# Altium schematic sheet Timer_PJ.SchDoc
size A4
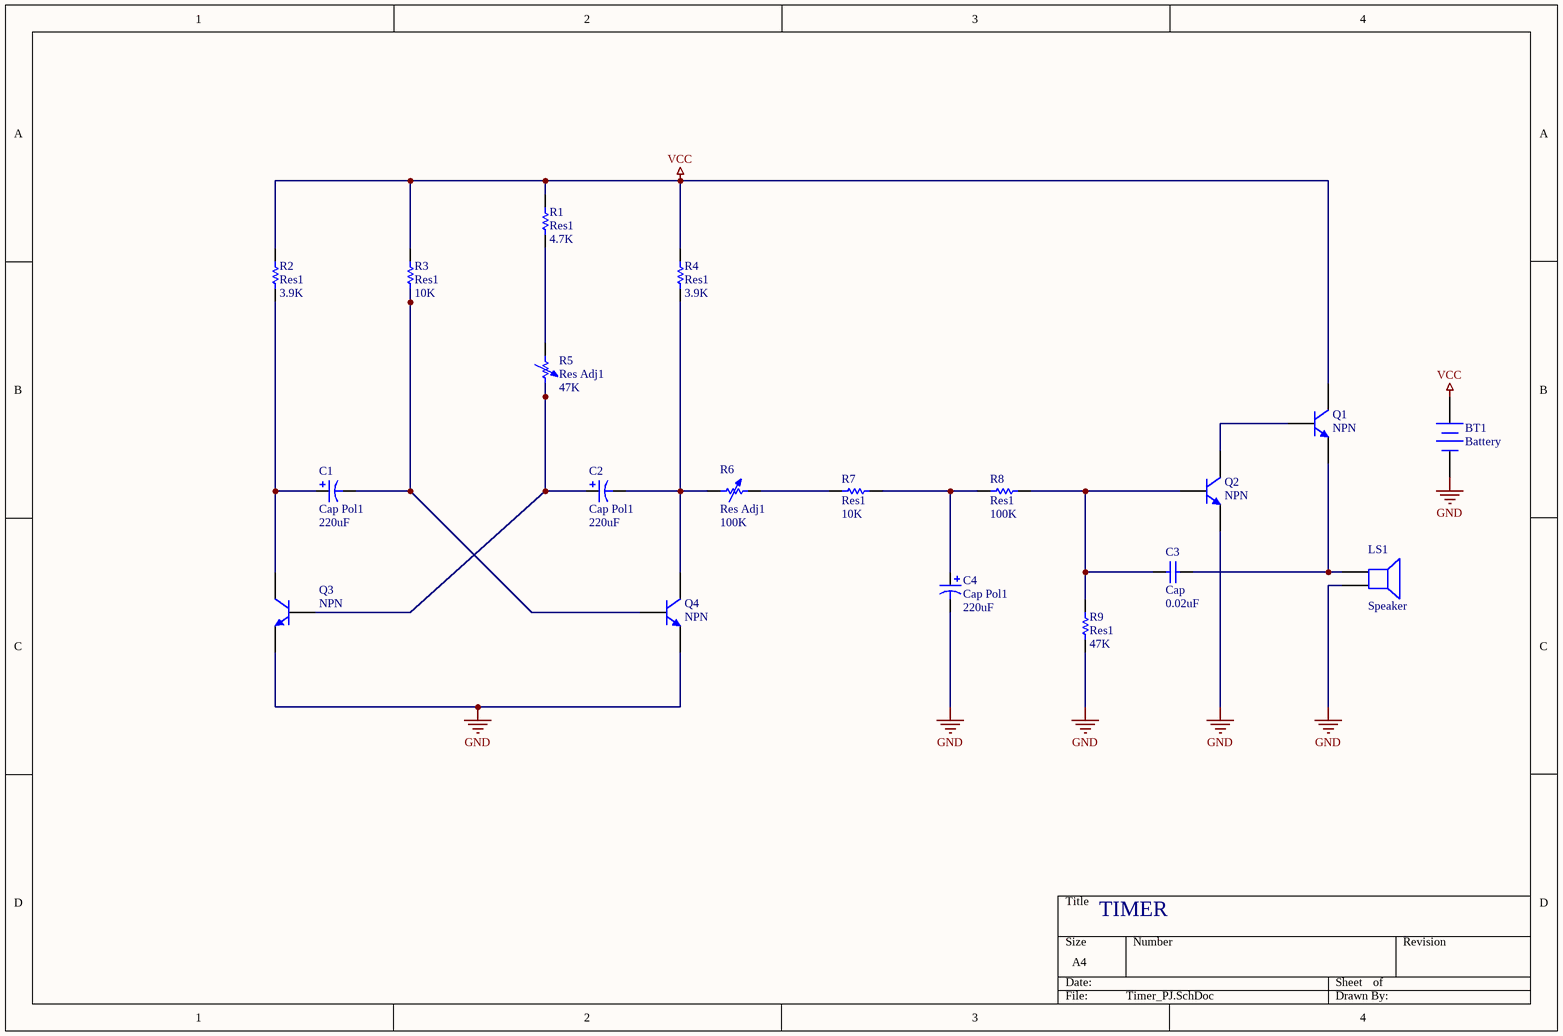
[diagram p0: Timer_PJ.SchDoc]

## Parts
BT1  Battery  [BAT-2]
C1  Cap Pol1  value 220uF  [RB7.6-15]
C2  Cap Pol1  value 220uF  [RB7.6-15]
C3  Cap  value 0.02uF  [RAD-0.3]
C4  Cap Pol1  value 220uF  [RB7.6-15]
LS1  Speaker  [PIN2]
Q1  NPN  [TO-226-AA]
Q2  NPN  [TO-226-AA]
Q3  NPN  [TO-226-AA]
Q4  NPN  [TO-226-AA]
R1  Res1  value 4.7K  [AXIAL-0.3]
R2  Res1  value 3.9K  [AXIAL-0.3]
R3  Res1  value 10K  [AXIAL-0.3]
R4  Res1  value 3.9K  [AXIAL-0.3]
R5  Res Adj1  value 47K  [AXIAL-0.7]
R6  Res Adj1  value 100K  [AXIAL-0.7]
R7  Res1  value 10K  [AXIAL-0.3]
R8  Res1  value 100K  [AXIAL-0.3]
R9  Res1  value 47K  [AXIAL-0.3]

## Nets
GND: BT1.2(-) C4.2 LS1.2 Q2.3(E) Q3.3(E) Q4.3(E) R9.2
VCC: BT1.1(+) Q1.1(C) R1.1 R2.1 R3.1 R4.1
NetC1_1: C1.1 Q3.1(C) R2.2
NetC1_2: C1.2 Q4.2(B) R3.2
NetC2_1: C2.1 Q3.2(B) R5.2
NetC2_2: C2.2 Q4.1(C) R4.2 R6.1
NetC3_1: C3.1 Q2.2(B) R8.1 R9.1
NetC3_2: C3.2 LS1.1 Q1.3(E)
NetC4_1: C4.1 R7.1 R8.2
NetQ1_2: Q1.2(B) Q2.1(C)
NetR1_2: R1.2 R5.1
NetR6_2: R6.2 R7.2

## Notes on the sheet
- TIMER

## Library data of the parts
BT1 = Battery: Multicell Battery
C1 C2 C4 = Cap Pol1: Polarized Capacitor (Radial)
C3 = Cap: Capacitor
LS1 = Speaker: Loudspeaker
Q1-Q4 = NPN: NPN Bipolar Transistor
R1-R4 R7-R9 = Res1: Resistor
R5 R6 = Res Adj1: Variable Resistor; Set Position: 0.5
